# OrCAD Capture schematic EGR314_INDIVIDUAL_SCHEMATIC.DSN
size A; title: Team 303 Display Screen Schematic; rev: 1; note: 1
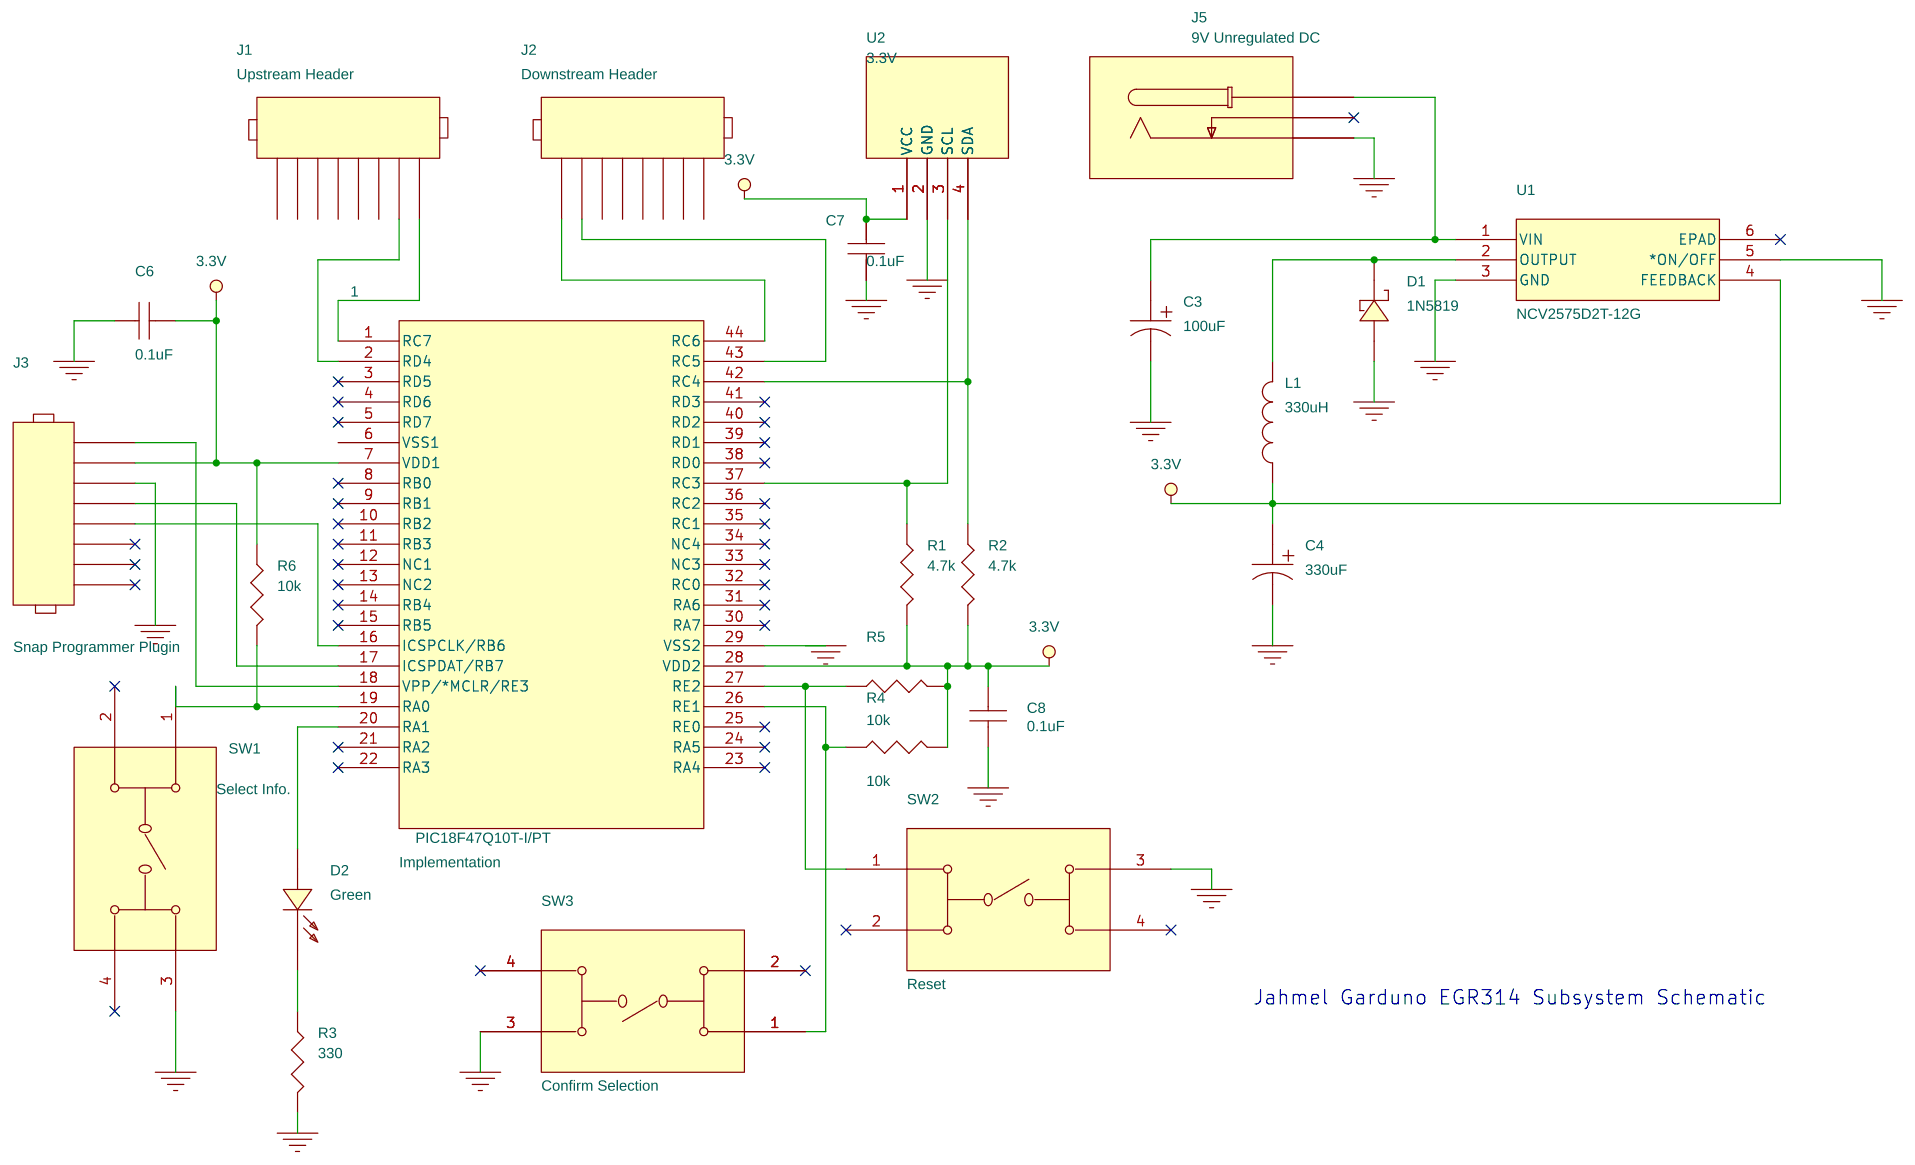
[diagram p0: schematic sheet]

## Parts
1  PIC18F47Q10T-I/PT
C3  100uF
C4  330uF
C6  0.1uF
C7  0.1uF
C8  0.1uF
D1  1N5819
D2  Green
J1  Upstream Header
J2  Downstream Header
J3  Snap Programmer Plugin
J5  9V Unregulated DC  [PJ-102A_CUD]
L1  330uH
R1  4.7k
R2  4.7k
R3  330
R4  10k
R5  10k
R6  10k
SW1  Select Info.  [SW4_1825910-B_TEC]
SW2  Reset  [SW4_1825910-B_TEC]
SW3  Confirm Selection  [SW4_1825910-B_TEC]
U1  NCV2575D2T-12G
U2  3.3V

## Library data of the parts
1 = PIC18F47Q10T-I_PT
C3 C4 = CAPACITOR_POL_SM
C6-C8 = CAP_NP
D1 = DIODE_SCHOTTKY
D2 = LED
J1-J3 = 8_HEADER
J5 = PJ-102A
L1 = INDUCTOR
R1-R6 = RESISTOR
SW1-SW3 = 1825910-6
U1 = NCV2575D2T-12G
U2 = Songhe_128x64_OLED_LED_Display

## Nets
3.3V: 1.7(VDD1) 1.28(VDD2) C4.1 C6.2 C7.1 C8.1 J3.2 L1.1 R1.2 R2.2 R4.2 R5.2 R6.1 U1.4(FEEDBACK) U2.1(VCC)
GND_POWER: 1.29(VSS2) C3.2 C4.2 C6.1 C7.2 C8.2 D1.1(ANODE) J3.3 J5.2 R3.2 SW1.3 SW2.3 SW3.3 U1.3(GND) U1.5(*ON/OFF) U2.2(GND)
VSS1: 1.6(VSS1)
N01808: C3.1 J5.1 U1.1(VIN)
N01826: D1.2(CATHODE) L1.2 U1.2(OUTPUT)
N03055: 1.37(RC3) R1.1 U2.3(SCL)
N03062: 1.42(RC4) R2.1 U2.4(SDA)
N03352: 1.1(RC7) J1.1
N03369: 1.44(RC6) J2.8
N05337: 1.18(VPP/*MCLR/RE3) J3.1
N05400: 1.19(RA0) R6.2 SW1.1
N05670: 1.20(RA1) D2.2(ANODE)
N05862: 1.27(RE2) R5.1 SW2.1
N06262: 1.26(RE1) R4.1 SW3.1
N06343: 1.2(RD4) J1.2
N06403: 1.43(RC5) J2.7
N08300: 1.17(ICSPDAT/RB7) J3.4
N08312: 1.16(ICSPCLK/RB6) J3.5
N13523: D2.1(CATHODE) R3.1

Not connected (* = marked no-connect by the designer): 1 3(RD5)* 4(RD6)* 5(RD7)* 8(RB0)* 9(RB1)* 10(RB2)* 11(RB3)* 12(NC1)* 13(NC2)* 14(RB4)* 15(RB5)* 21(RA2)* 22(RA3)* 23(RA4)* 24(RA5)* 25(RE0)* 30(RA7)* 31(RA6)* 32(RC0)* 33(NC3)* 34(NC4)* 35(RC1)* 36(RC2)* 38(RD0)* 39(RD1)* 40(RD2)* 41(RD3)*; J1 3 4 5 6 7 8; J2 1 2 3 4 5 6; J3 6* 7* 8*; J5 3*; SW1 2* 4*; SW2 2* 4*; SW3 2* 4*; U1 6(EPAD)*

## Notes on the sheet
- Jahmel Garduno EGR314 Subsystem Schematic
